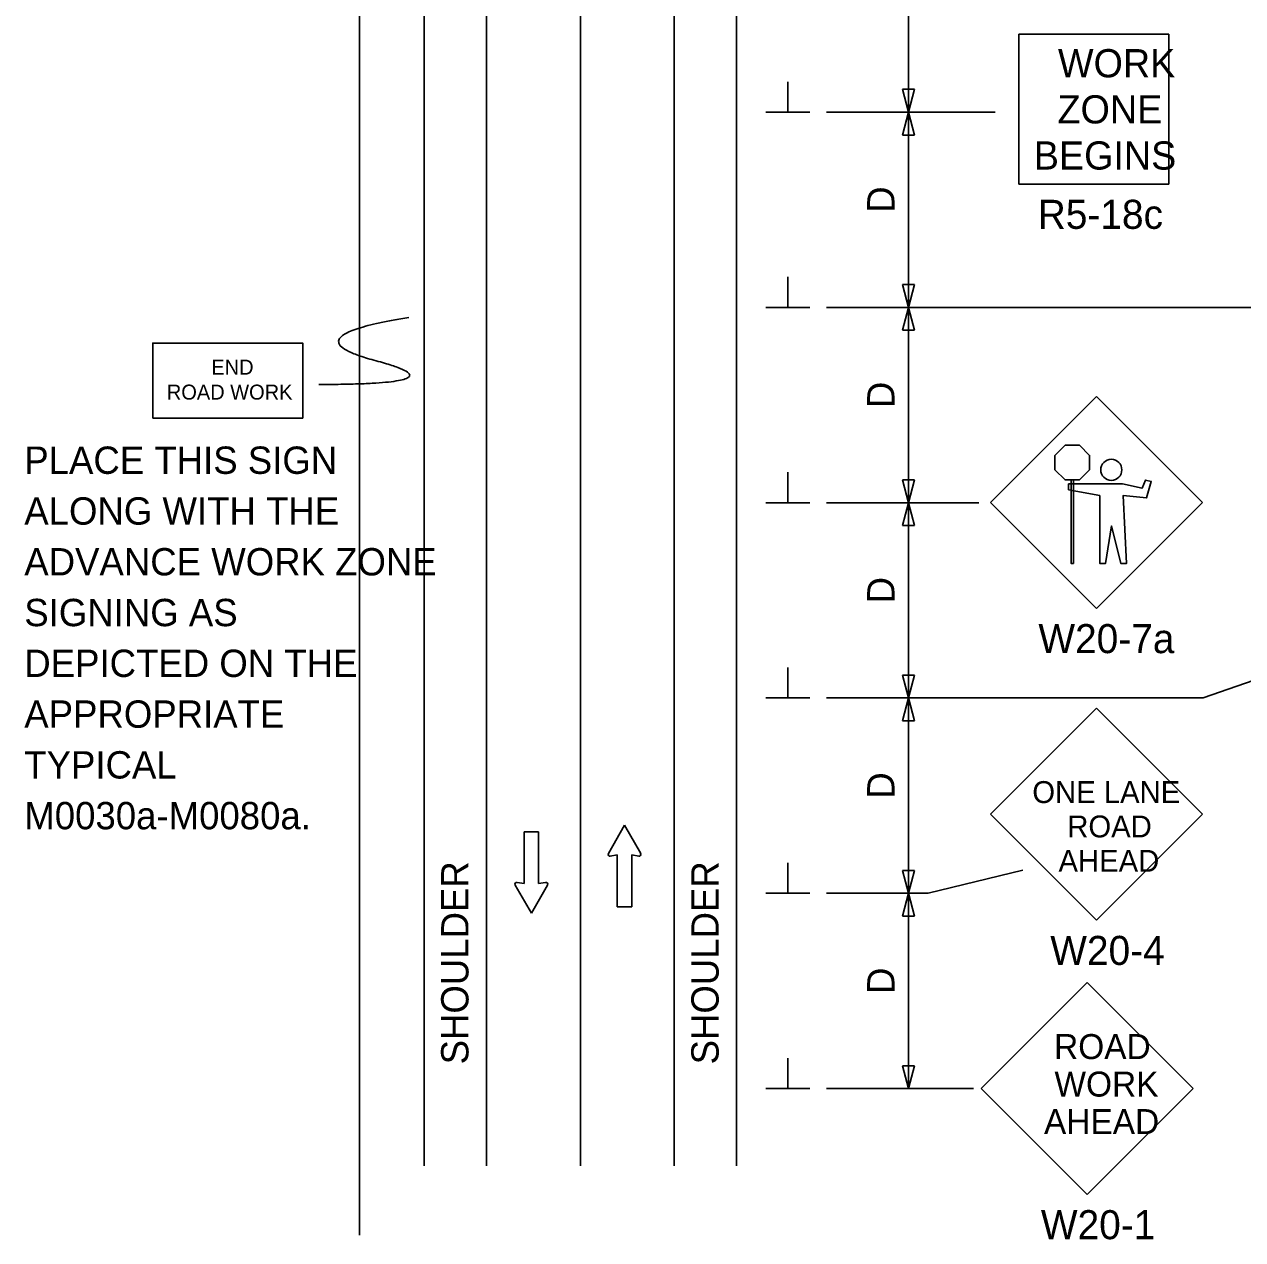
# Model space of a CAD drawing. Extents: x 16735 to 19510, y 5880 to 6929.
# Drawn here: x 16735.5 to 17047.4, y 5958.6 to 6269.8 of the extents above; entities that cross this region are included whole.
import ezdxf

# ---------------------------------------------------------------- set-up
doc = ezdxf.new("R2010")
doc.units = 0
for name, color, linetype in [('ALI_LEGAL_EX', 7, 'Continuous'), ('BORDER', 7, 'Continuous'), ('MT_SCRATCH_LEVEL_E', 7, 'Continuous'), ('SCRATCH_LEVEL_A', 7, 'Continuous'), ('TRAFFIC_SIGNS_PR', 7, 'Continuous')]:
    doc.layers.add(name, color=color, linetype=linetype)

msp = doc.modelspace()

# ---------------------------------------------------------------- linework, layer by layer
at = {"layer": 'ALI_LEGAL_EX'}
msp.add_line((16821.31, 5959.79), (16821.31, 6316.41), dxfattribs=at)
at = {"layer": 'BORDER'}
for p, q in [((16837.83, 6357.23), (16837.83, 5977.53)), ((16853.83, 6357.23), (16853.83, 5977.53)), ((16901.83, 6357.23), (16901.83, 5977.53)), ((16917.83, 6357.23), (16917.83, 5977.53)), ((16821.31, 5959.79), (16821.31, 6339.5)), ((16877.83, 5977.53), (16877.83, 6334.14))]:
    msp.add_line(p, q, dxfattribs=at)
for points in [[(16877.83, 6177.53), (16877.83, 6202.53)], [(16877.83, 6177.53), (16877.83, 6202.53)], [(16877.83, 6077.53), (16877.83, 6102.53)], [(16877.83, 6077.53), (16877.83, 6102.53)], [(16877.83, 5977.53), (16877.83, 6002.53)], [(16877.83, 5977.53), (16877.83, 6002.53)]]:
    msp.add_lwpolyline(points, dxfattribs=at)
at = {"layer": 'MT_SCRATCH_LEVEL_E'}
for p, q in [((16867.14, 6063.03), (16863.4, 6063.03)), ((16863.4, 6063.03), (16863.4, 6049.78)), ((16867.14, 6063.03), (16863.4, 6063.03)), ((16863.4, 6063.03), (16863.4, 6049.78)), ((16867.14, 6049.78), (16867.14, 6063.03)), ((16867.14, 6049.78), (16867.14, 6063.03)), ((16889.11, 6064.72), (16885, 6057.48)), ((16889.11, 6064.72), (16885, 6057.48)), ((16893.26, 6057.48), (16889.11, 6064.72)), ((16893.26, 6057.48), (16889.11, 6064.72)), ((16885.48, 6056.8), (16887.26, 6057.11)), ((16885.48, 6056.8), (16887.26, 6057.11)), ((16887.26, 6057.11), (16887.26, 6043.86)), ((16887.26, 6057.11), (16887.26, 6043.86)), ((16891, 6043.86), (16891, 6057.11)), ((16891, 6057.11), (16892.78, 6056.8)), ((16891, 6043.86), (16891, 6057.11)), ((16891, 6057.11), (16892.78, 6056.8)), ((16861.15, 6049.41), (16865.29, 6042.17)), ((16861.15, 6049.41), (16865.29, 6042.17)), ((16863.4, 6049.78), (16861.62, 6050.09)), ((16863.4, 6049.78), (16861.62, 6050.09)), ((16865.29, 6042.17), (16869.4, 6049.41)), ((16865.29, 6042.17), (16869.4, 6049.41)), ((16868.92, 6050.09), (16867.14, 6049.78)), ((16868.92, 6050.09), (16867.14, 6049.78)), ((16887.26, 6043.86), (16891, 6043.86)), ((16887.26, 6043.86), (16891, 6043.86))]:
    msp.add_line(p, q, dxfattribs=at)
for centre, start, end in [((16885.41, 6057.26), 150.4248, 279.9638), ((16885.41, 6057.26), 150.4248, 279.9638), ((16892.85, 6057.26), 260.0362, 29.7731), ((16892.85, 6057.26), 260.0362, 29.7731), ((16861.55, 6049.63), 80.0362, 209.7731), ((16861.55, 6049.63), 80.0362, 209.7731), ((16869, 6049.63), 330.4248, 99.9638), ((16869, 6049.63), 330.4248, 99.9638)]:
    msp.add_arc(centre, 0.463, start, end, dxfattribs=at)
at = {"layer": 'SCRATCH_LEVEL_A'}
for p, q in [((16990.09, 6228.85), (16990.09, 6267.25)), ((16990.09, 6267.25), (17028.49, 6267.25)), ((17028.49, 6228.85), (17028.49, 6267.25)), ((16990.09, 6228.85), (17028.49, 6228.85)), ((17009.93, 6174.53), (16982.78, 6147.38)), ((17037.08, 6147.38), (17009.93, 6174.53)), ((16982.78, 6147.38), (17009.93, 6120.22)), ((17009.93, 6120.22), (17037.08, 6147.38)), ((17009.93, 6094.69), (16982.78, 6067.54)), ((17037.09, 6067.54), (17009.93, 6094.69)), ((16982.78, 6067.54), (17009.93, 6040.39)), ((17009.93, 6040.39), (17037.09, 6067.54)), ((17007.54, 6024.47), (16980.39, 5997.32)), ((17034.7, 5997.32), (17007.54, 6024.47)), ((16980.39, 5997.32), (17007.54, 5970.17)), ((17007.54, 5970.17), (17034.7, 5997.32))]:
    msp.add_line(p, q, dxfattribs=at)
for points in [[(16768.35, 6168.96), (16806.75, 6168.96), (16806.75, 6188.16), (16768.35, 6188.16)], [(17001.89, 6162.01), (17005.57, 6162.01), (17008.17, 6159.41), (17008.17, 6155.74), (17005.57, 6153.14), (17001.89, 6153.14), (16999.3, 6155.74), (16999.3, 6159.41)], [(17016.61, 6152.1), (17002.79, 6152.1), (17002.79, 6150.6), (17010.76, 6149.14), (17010.76, 6131.74), (17012.26, 6131.74), (17013.76, 6141.34), (17016.16, 6131.74), (17017.66, 6131.74), (17016.76, 6149.14), (17022.76, 6148.54), (17023.96, 6152.74), (17022.5, 6153.11), (17021.6, 6151.01)], [(17003.43, 6153.14), (17003.43, 6131.76), (17004.03, 6131.76), (17004.03, 6153.14)]]:
    msp.add_lwpolyline(points, close=True, dxfattribs=at)
msp.add_circle((17013.74, 6155.71), 2.7, dxfattribs=at)
msp.add_open_spline([(16810.87, 6177.57), (16848.26, 6177.57), (16802.77, 6189.69), (16833.92, 6194.74)], degree=2, dxfattribs=at)
at = {"layer": 'TRAFFIC_SIGNS_PR'}
for p, q in [((16961.83, 6297.3), (16961.83, 6247.3)), ((16930.95, 6247.3), (16930.95, 6255.09)), ((16961.83, 6247.3), (16960.26, 6253.16)), ((16960.26, 6253.16), (16961.83, 6253.16)), ((16961.83, 6247.3), (16960.26, 6253.16)), ((16960.26, 6253.16), (16961.83, 6253.16)), ((16961.83, 6253.16), (16963.4, 6253.16)), ((16963.4, 6253.16), (16961.83, 6247.3)), ((16961.83, 6253.16), (16963.4, 6253.16)), ((16963.4, 6253.16), (16961.83, 6247.3)), ((16936.58, 6247.3), (16925.33, 6247.3)), ((16940.83, 6247.3), (16983.97, 6247.3)), ((16960.26, 6241.44), (16961.83, 6247.3)), ((16960.26, 6241.44), (16961.83, 6247.3)), ((16961.83, 6247.3), (16963.4, 6241.44)), ((16961.83, 6247.3), (16963.4, 6241.44)), ((16961.83, 6247.3), (16961.83, 6197.3)), ((16961.83, 6241.44), (16960.26, 6241.44)), ((16961.83, 6241.44), (16960.26, 6241.44)), ((16963.4, 6241.44), (16961.83, 6241.44)), ((16963.4, 6241.44), (16961.83, 6241.44)), ((16930.95, 6197.3), (16930.95, 6205.09)), ((16961.83, 6197.3), (16960.26, 6203.16)), ((16960.26, 6203.16), (16961.83, 6203.16)), ((16961.83, 6197.3), (16960.26, 6203.16)), ((16960.26, 6203.16), (16961.83, 6203.16)), ((16961.83, 6203.16), (16963.4, 6203.16)), ((16963.4, 6203.16), (16961.83, 6197.3)), ((16961.83, 6203.16), (16963.4, 6203.16)), ((16963.4, 6203.16), (16961.83, 6197.3)), ((16936.58, 6197.3), (16925.33, 6197.3)), ((16940.83, 6197.3), (17051.85, 6197.3)), ((16960.26, 6191.44), (16961.83, 6197.3)), ((16960.26, 6191.44), (16961.83, 6197.3)), ((16961.83, 6197.3), (16961.83, 6147.3)), ((16961.83, 6197.3), (16963.4, 6191.44)), ((16961.83, 6197.3), (16963.4, 6191.44)), ((16961.83, 6191.44), (16960.26, 6191.44)), ((16961.83, 6191.44), (16960.26, 6191.44)), ((16963.4, 6191.44), (16961.83, 6191.44)), ((16963.4, 6191.44), (16961.83, 6191.44)), ((16930.95, 6147.3), (16930.95, 6155.09)), ((16961.83, 6147.3), (16960.26, 6153.16)), ((16960.26, 6153.16), (16961.83, 6153.16)), ((16961.83, 6147.3), (16960.26, 6153.16)), ((16960.26, 6153.16), (16961.83, 6153.16)), ((16961.83, 6153.16), (16963.4, 6153.16)), ((16963.4, 6153.16), (16961.83, 6147.3)), ((16961.83, 6153.16), (16963.4, 6153.16)), ((16963.4, 6153.16), (16961.83, 6147.3)), ((16936.58, 6147.3), (16925.33, 6147.3)), ((16940.83, 6147.3), (16979.83, 6147.3)), ((16960.26, 6141.44), (16961.83, 6147.3)), ((16960.26, 6141.44), (16961.83, 6147.3)), ((16961.83, 6147.3), (16961.83, 6097.3)), ((16961.83, 6147.3), (16963.4, 6141.44)), ((16961.83, 6147.3), (16963.4, 6141.44)), ((16961.83, 6141.44), (16960.26, 6141.44)), ((16961.83, 6141.44), (16960.26, 6141.44)), ((16963.4, 6141.44), (16961.83, 6141.44)), ((16963.4, 6141.44), (16961.83, 6141.44)), ((16930.95, 6097.3), (16930.95, 6105.09)), ((17037.22, 6097.3), (17063.1, 6106.27)), ((16961.83, 6097.3), (16960.26, 6103.16)), ((16960.26, 6103.16), (16961.83, 6103.16)), ((16961.83, 6097.3), (16960.26, 6103.16)), ((16960.26, 6103.16), (16961.83, 6103.16)), ((16961.83, 6103.16), (16963.4, 6103.16)), ((16963.4, 6103.16), (16961.83, 6097.3)), ((16961.83, 6103.16), (16963.4, 6103.16)), ((16963.4, 6103.16), (16961.83, 6097.3)), ((16936.58, 6097.3), (16925.33, 6097.3)), ((16940.83, 6097.3), (17037.22, 6097.3)), ((16960.26, 6091.44), (16961.83, 6097.3)), ((16960.26, 6091.44), (16961.83, 6097.3)), ((16961.83, 6097.3), (16961.83, 6047.3)), ((16961.83, 6097.3), (16963.4, 6091.44)), ((16961.83, 6097.3), (16963.4, 6091.44)), ((16961.83, 6091.44), (16960.26, 6091.44)), ((16961.83, 6091.44), (16960.26, 6091.44)), ((16963.4, 6091.44), (16961.83, 6091.44)), ((16963.4, 6091.44), (16961.83, 6091.44)), ((16930.95, 6047.3), (16930.95, 6055.09)), ((16961.83, 6047.3), (16960.26, 6053.16)), ((16960.26, 6053.16), (16961.83, 6053.16)), ((16961.83, 6047.3), (16960.26, 6053.16)), ((16960.26, 6053.16), (16961.83, 6053.16)), ((16961.83, 6053.16), (16963.4, 6053.16)), ((16963.4, 6053.16), (16961.83, 6047.3)), ((16961.83, 6053.16), (16963.4, 6053.16)), ((16963.4, 6053.16), (16961.83, 6047.3)), ((16966.83, 6047.3), (16991.1, 6053.24)), ((16936.58, 6047.3), (16925.33, 6047.3)), ((16940.83, 6047.3), (16966.83, 6047.3)), ((16960.26, 6041.44), (16961.83, 6047.3)), ((16960.26, 6041.44), (16961.83, 6047.3)), ((16961.83, 6047.3), (16961.83, 5997.3)), ((16961.83, 6047.3), (16963.4, 6041.44)), ((16961.83, 6047.3), (16963.4, 6041.44)), ((16961.83, 6041.44), (16960.26, 6041.44)), ((16961.83, 6041.44), (16960.26, 6041.44)), ((16963.4, 6041.44), (16961.83, 6041.44)), ((16963.4, 6041.44), (16961.83, 6041.44)), ((16930.95, 5997.3), (16930.95, 6005.09)), ((16961.83, 5997.3), (16960.26, 6003.16)), ((16960.26, 6003.16), (16961.83, 6003.16)), ((16961.83, 6003.16), (16963.4, 6003.16)), ((16963.4, 6003.16), (16961.83, 5997.3)), ((16936.58, 5997.3), (16925.33, 5997.3)), ((16940.83, 5997.3), (16978.44, 5997.3))]:
    msp.add_line(p, q, dxfattribs=at)

# ---------------------------------------------------------------- texts
at = {"layer": 'SCRATCH_LEVEL_A'}
for s, height, p in [('WORK', 7.217, (17000.09, 6256.21)), ('ZONE', 7.217, (16999.97, 6244.4)), ('BEGINS', 7.217, (16993.9, 6232.59)), ('R5-18c', 7.44, (16994.9, 6217.41)), ('END', 3.831, (16783.35, 6180.09)), ('ROAD WORK', 3.831, (16771.96, 6173.7)), ('W20-7a', 7.44, (16995.07, 6108.78)), ('ONE LANE', 5.6, (16993.52, 6070.41)), ('ROAD', 5.6, (17002.47, 6061.61)), ('AHEAD', 5.6, (17000.22, 6052.81)), ('W20-4', 7.44, (16998.11, 6028.95)), ('ROAD', 6.4, (16999.09, 6004.85)), ('WORK', 6.4, (16999.19, 5995.25)), ('AHEAD', 6.4, (16996.51, 5985.65)), ('W20-1', 7.44, (16995.71, 5958.73))]:
    msp.add_text(s, height=height, dxfattribs=at).set_placement(p)
for s, p in [('PLACE THIS SIGN ', (16735.47, 6154.68)), ('ALONG WITH THE', (16735.47, 6141.68)), ('ADVANCE WORK ZONE ', (16735.47, 6128.68)), ('SIGNING AS', (16735.47, 6115.68)), ('DEPICTED ON THE ', (16735.47, 6102.68)), ('APPROPRIATE', (16735.47, 6089.68)), ('TYPICAL ', (16735.47, 6076.68)), ('M0030a-M0080a.', (16735.47, 6063.68))]:
    msp.add_text(s, height=7, rotation=360, dxfattribs=at).set_placement(p)
at = {"layer": 'TRAFFIC_SIGNS_PR'}
for s, p in [('D', (16958.24, 6221.52)), ('D', (16958.24, 6171.52)), ('D', (16958.24, 6121.52)), ('D', (16958.24, 6071.52)), ('SHOULDER', (16849.18, 6003.49)), ('SHOULDER', (16913.23, 6003.49)), ('D', (16958.24, 6021.52))]:
    msp.add_text(s, height=7, rotation=90, dxfattribs=at).set_placement(p)

doc.saveas('drawing.dxf')
